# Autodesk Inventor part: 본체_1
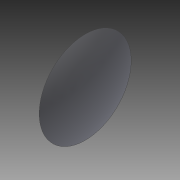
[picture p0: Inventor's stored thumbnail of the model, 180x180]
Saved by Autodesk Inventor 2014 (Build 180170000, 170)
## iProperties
Created: 2016-04
Part Number: 본체_1
Material: Generic
Document SubType Name: Modeling
Designer: user
Density: 1 g/cm^3
Appearance: Default
Author: user
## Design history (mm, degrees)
sketch "Sketch1"
  geometry: L1 (45.841, 110.899)-(-45.841, -110.899); A1 r 120 centre (0, 0) between (45.841, 110.899) and (-45.841, -110.899); 1 further point
  constraints: 2 end point, 2 point on circle, 1 centre point, 1 coincident, 1 midpoint
  dimensions: "d0" = 240 diameter of A1
revolve "Revolution1" sketch "Sketch1" stored, may be unused: angle "d1" = 90 deg
sketch "Sketch2"
  geometry: L1 (109.378, 41.54)-(-109.378, -41.54); A1 r 117 centre (0, 0) between (109.378, 41.54) and (-109.378, -41.54); 1 further point
  constraints: 2 end point, 2 point on circle, 1 centre point, 1 coincident, 1 midpoint
  dimensions: "d2" = 234 diameter of A1
revolve "Revolution2" sketch "Sketch2" stored, may be unused: angle "d3" = 90 deg
workplane "Work Plane1"
sketch "Sketch3"
  geometry: L1 (-186.134, 164.451)-(186.134, 164.451); L2 (186.134, 164.451)-(186.134, -164.451); L3 (186.134, -164.451)-(-186.134, -164.451); L4 (-186.134, -164.451)-(-186.134, 164.451); 3 further points
  constraints: 8 end point, 2 midpoint, 2 parallel, 1 horizontal, 1 horizontal alignment, 1 perpendicular, 1 vertical alignment
  dimensions: "d5" = 372.26754 distance of L1.start L1.end; "d6" = 328.90283 distance of L3.end L1.start
extrude "Extrusion1" cut sketch "Sketch3" distance "d7" = 11111; taper "d8" = 0 deg
body "Solid1"
